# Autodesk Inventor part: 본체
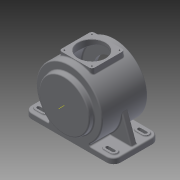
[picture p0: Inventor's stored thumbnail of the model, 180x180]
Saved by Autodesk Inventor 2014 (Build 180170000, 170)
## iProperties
Created: 2015-06
Part Number: 본체
Material: Generic
Document SubType Name: Modeling
Designer: 시험용
Density: 1 g/cm^3
Appearance: Default
Mass: 1210.29 g
Surface Area: 2309.95 cm^2
Volume: 1210.29 cm^3
Author: 시험용
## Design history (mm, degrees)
sketch "스케치1"
  geometry: 1 further point
sketch "스케치2"
  geometry: L1 (-115, 59)-(115, 59); L2 (115, 59)-(115, -59); L3 (115, -59)-(-115, -59); L4 (-115, -59)-(-115, 59); 5 further points
  constraints: 8 end point, 4 midpoint, 2 horizontal alignment, 2 parallel, 2 vertical alignment, 1 horizontal, 1 perpendicular
  dimensions: "d0" = 230 distance of L1.start L1.end; "d1" = 118 distance of L1.end L2.end
extrude "돌출1" new body sketch "스케치2" stored distance "d2" = 14; taper "d3" = 0 deg
sketch "스케치5"
  geometry: L1 (230, -14)-(0, -14) reference; C1 r 85 at (115, 71); 1 further point
  constraints: 1 centre point, 1 tangent, 1 vertical alignment
  dimensions: "d7" = 170 diameter of C1
extrude "돌출3" join sketch "스케치5" distance "d8" = 118; taper "d9" = 0 deg
sketch "스케치6"
  geometry: C1 r 65 at (115, 85); A1 r 85 centre (115, 85) between (161.733, 14) and (68.267, 14) reference; 1 further point
  constraints: 1 centre point, 1 coincident
  dimensions: "d10" = 130 diameter of C1
extrude "돌출4" join sketch "스케치6" distance "d11" = 13; taper "d12" = 0 deg
sketch "스케치7"
  geometry: C1 r 65 at (115, -85); A1 r 85 centre (115, -85) between (68.267, -14) and (161.733, -14) reference; 1 further point
  constraints: 1 centre point, 1 coincident
  dimensions: "d13" = 130 diameter of C1
extrude "돌출5" join sketch "스케치7" distance "d14" = 3; taper "d15" = 0 deg
node "작업 평면1"
sketch "스케치8"
  geometry: L1 (-42.5, 42.5)-(42.5, 42.5); L2 (42.5, 42.5)-(42.5, -42.5); L3 (42.5, -42.5)-(-42.5, -42.5); L4 (-42.5, -42.5)-(-42.5, 42.5); 5 further points
  constraints: 8 end point, 4 midpoint, 2 horizontal alignment, 2 parallel, 2 vertical alignment, 1 horizontal, 1 perpendicular
  dimensions: "d17" = 85 distance of L2.end L3.end; "d18" = 85 distance of L3.end L1.start
extrude "돌출6" join sketch "스케치8" stored distance "d19" = 3; taper "d20" = 0 deg
sketch "스케치9"
  geometry: C1 r 35 at (0, 0); 1 further point
  constraints: 1 centre point, 1 coincident
  dimensions: "d21" = 70 diameter of C1
extrude "돌출7" cut sketch "스케치9" distance "d22" = 20; taper "d23" = 0 deg
sketch "스케치11"
  geometry: L1 (59, 143)-(62, 143) reference; L2 (62, 143)-(62, 13) reference; L3 (35, 166)-(42.5, 166) reference; L4 (42.5, 166)-(42.5, 163) reference; L5 (42.5, 163)-(59, 163) reference; L6 (59, 163)-(59, 143) reference; L7 (-72, 143)-(-59, 143) reference; L8 (-59, 143)-(-59, 163) reference; L9 (-59, 163)-(-42.5, 163) reference; L10 (-42.5, 163)-(-42.5, 166) reference; L11 (-42.5, 166)-(-35, 166) reference; L12 (62, 13)-(59, 13) reference; L13 (59, 13)-(59, -7) reference; L14 (59, -7)-(-59, -7) reference; L15 (-59, -7)-(-59, 13) reference; L16 (-59, 13)-(-72, 13) reference; L17 (-72, 13)-(-72, 143) reference; L18 (-35, 166)-(-35, 146) reference; L19 (-35, 146)-(35, 146) reference; L20 (35, 146)-(35, 166) reference; L21 (-72, 78)-(62, 78); L22 (62, 125.5)-(51, 125.5); L23 (51, 125.5)-(51, 155); L24 (51, 155)-(-51, 155); L25 (-51, 155)-(-51, 110.632); L26 (-51, 110.632)-(-47.5, 109); L27 (-47.5, 109)-(-47.5, 101.5); L28 (-47.5, 101.5)-(-61.5, 101.5); L29 (-61.5, 101.5)-(-61.5, 93); L30 (-61.5, 93)-(-64.5, 93); L31 (-64.5, 93)-(-64.5, 78); 1 further point
  constraints: 22 end point, 7 parallel, 2 midpoint, 2 point on line, 1 perpendicular, 1 vertical
  dimensions: "d51" = 95 diameter of L22 L21; "d52" = 154 diameter of L24 L21; "d53" = 47 diameter of L28 L21; "d54" = 115 deg angle of L26 L25; "d55" = 62 diameter of L26.end L21; "d56" = 3.5 horizontal distance of L26.end L25.end; "d57" = 30 diameter of L30 L21; "d58" = 3 distance from line of L29.end L31; "d59" = 14 horizontal distance of L27.end L29.end; "d60" = 11 distance of L22.start L22.end; "d62" = 102 distance between parallel lines of L23 L25
revolve "회전1" sketch "스케치11" stored, may be unused: angle "d63" = 90 deg
chamfer "모따기1" distance "d64" = 1; stored, may be unused: second distance "d65" = 2, angle "d66" = 45 deg
sketch "스케치12"
  geometry: C1 r 36 at (0, 0) reference; 1 further point
  dimensions: "d67" = 35.5 horizontal distance of C1.centre point (-35.5, 35.5); "d68" = 35.5 horizontal distance of C1.centre point (-35.5, 35.5)
hole "구멍4" sketch "스케치12" at (-35.5, 35.5) diameter "d69" = 3.242; stored, may be unused: countersink angle "d73" = 90 deg, drill point angle "d75" = 118 deg; dims "d70" = 10, "d71" = 47, "d72" = 14, "d74" = 13
sketch "스케치13" dims "d82" = 110
  geometry: C1 r 47.5 at (0, 0) reference; C2 r 65 at (0, 0) reference; 3 further points
  constraints: 2 vertical alignment, 1 coincident, 2 other
hole "구멍5" sketch "스케치13" at (0, -55) diameter "d83" = 3.242; stored, may be unused: countersink angle "d87" = 90 deg, drill point angle "d89" = 0 deg; dims "d84" = 11, "d85" = 47, "d86" = 14, "d88" = 13
sketch "스케치15"
  geometry: L1 (115, -7)-(-115, -7) reference; L2 (-115, -7)-(-115, 7) reference; L3 (-115, 7)-(-46.733, 7) reference; L4 (-42.5, 151.612)-(-42.5, 166) reference; L5 (-42.5, 166)-(-36, 166) reference; L6 (-36, 166)-(-35, 165) reference; L7 (-35, 165)-(-35, 146.586) reference; L8 (35, 146.586)-(35, 165) reference; L9 (35, 165)-(36, 166) reference; L10 (36, 166)-(42.5, 166) reference; L11 (42.5, 166)-(42.5, 151.612) reference; L12 (46.733, 7)-(115, 7) reference; L13 (115, 7)-(115, -7) reference; L14 (-84.87, 73.297)-(-109, 7); A1 r 85 centre (0, 78) between (-42.5, 151.612) and (-46.733, 7) reference; A2 r 85 centre (0, 78) between (46.733, 7) and (42.5, 151.612) reference; A3 r 77 centre (0, 78) between (-35, 146.586) and (35, 146.586) reference; 1 further point
  constraints: 2 end point, 1 point on circle, 1 point on line
  dimensions: "d93" = 110 deg angle of L14 L3; "d94" = 6 distance from line of L14.end L2
feature "리브1" sketch "스케치15" dims "d95" = 1, "d96" = 15, "d97" = 0, "d98" = 0, "d99" = 1, "d100" = 1
sketch "스케치16"
  geometry: L1 (115, -59)-(115, 59) reference; L2 (115, 59)-(46.733, 59) reference; L3 (46.733, -7.5)-(46.733, -59) reference; L4 (115, -59)-(46.733, -59) reference; L5 (115, 59)-(115, -59) reference; L6 (46.733, 59)-(115, 59) reference; L7 (-46.733, 59)-(46.733, 59) reference; L8 (-115, 59)-(-46.733, 59) reference; L9 (-115, -59)-(-115, 59) reference; L10 (-46.733, -59)-(-115, -59) reference; L11 (46.733, -59)-(-46.733, -59) reference; L12 (109, -7.5)-(46.733, -7.5) reference; L13 (109, 7.5)-(109, -7.5) reference; L14 (46.733, 7.5)-(109, 7.5) reference; L15 (46.733, 59)-(46.733, 7.5) reference; L16 (-46.733, 7.5)-(-46.733, 59) reference; L17 (-109, 7.5)-(-46.733, 7.5) reference; L18 (-109, -7.5)-(-109, 7.5) reference; L19 (-46.733, -7.5)-(-109, -7.5) reference; L20 (-46.733, -59)-(-46.733, -7.5) reference; L21 (29.799, -51)-(29.799, 51) reference; L22 (29.799, 51)-(-29.799, 51) reference; L23 (-29.799, 51)-(-29.799, -51) reference; L24 (-29.799, -51)-(29.799, -51) reference; L25 (81, 32)-(97, 32); L26 (97, 50)-(81, 50); L27 (46.733, -7.5)-(46.733, -59) reference; L28 (115, -59)-(46.733, -59) reference; L29 (115, 59)-(115, -59) reference; L30 (46.733, 59)-(115, 59) reference; L31 (-46.733, 59)-(46.733, 59) reference; L32 (-115, 59)-(-46.733, 59) reference; L33 (-115, -59)-(-115, 59) reference; L34 (-46.733, -59)-(-115, -59) reference; L35 (46.733, -59)-(-46.733, -59) reference; L36 (109, -7.5)-(46.733, -7.5) reference; L37 (109, 7.5)-(109, -7.5) reference; L38 (46.733, 7.5)-(109, 7.5) reference; L39 (46.733, 59)-(46.733, 7.5) reference; L40 (-46.733, 7.5)-(-46.733, 59) reference; L41 (-109, 7.5)-(-46.733, 7.5) reference; L42 (-109, -7.5)-(-109, 7.5) reference; L43 (-46.733, -7.5)-(-109, -7.5) reference; L44 (-46.733, -59)-(-46.733, -7.5) reference; L45 (29.799, -51)-(29.799, 51) reference; L46 (29.799, 51)-(-29.799, 51) reference; L47 (-29.799, 51)-(-29.799, -51) reference; L48 (-29.799, -51)-(29.799, -51) reference; A1 r 9 centre (97, 41) between (97, 32) and (97, 50); A2 r 9 centre (81, 41) between (81, 50) and (81, 32); 1 further point
  constraints: 4 end point, 4 point on circle, 4 tangent, 2 centre point, 2 parallel
  dimensions: "d102" = 18 distance from line of L2 A1.centre; "d103" = 16 distance of A2.centre A1.centre; "d104" = 18 distance between parallel lines of L25 L26; "d105" = 18 distance from line of L1 A1.centre
extrude "돌출8" join sketch "스케치16" distance "d106" = 3; taper "d107" = 0 deg
sketch "스케치17"
  geometry: L1 (81, 32)-(97, 32) reference; L2 (97, 50)-(81, 50) reference; L3 (81, 45)-(97, 45); L4 (97, 37)-(81, 37); A1 r 9 centre (97, 41) between (97, 32) and (97, 50) reference; A2 r 9 centre (81, 41) between (81, 50) and (81, 32) reference; A3 r 4 centre (97, 41) between (97, 37) and (97, 45); A4 r 4 centre (81, 41) between (81, 45) and (81, 37); 1 further point
  constraints: 4 end point, 4 point on circle, 2 centre point, 3 other
  dimensions: "d108" = 8 distance between parallel lines of L4 L3
extrude "돌출9" cut sketch "스케치17" stored distance "d109" = 15; taper "d110" = 0 deg
fillet "모깎기1" dims "d111" = 3
fillet "모깎기2" dims "d118" = 18
fillet "모깎기3" dims "d119" = 3
fillet "모깎기4" dims "d120" = 7
fillet "모깎기5" dims "d121" = 3
node "작업 평면5"
  node "작업 평면4"
sketch "스케치19"
  geometry: L1 (-10.5, -44.598)-(-10.5, 20.042) reference; L2 (-56, -44.598)-(-10.5, -44.598) reference; L3 (-56, -82.329)-(-56, -44.598) reference; L4 (-10.5, -82.329)-(-56, -82.329) reference; L5 (-10.5, -39.601)-(-10.5, -82.329) reference; L6 (10.5, -39.601)-(-10.5, -39.601) reference; L7 (10.5, -82.329)-(10.5, -39.601) reference; L8 (56, -82.329)-(10.5, -82.329) reference; L9 (56, -36.727)-(56, -82.329) reference; L10 (10.5, -36.727)-(56, -36.727) reference; L11 (10.5, 20.042)-(10.5, -36.727) reference; L12 (-4.5, 32.161)-(4.5, 32.161) reference; L13 (-45.5, 84.981)-(-45.5, 55.998) reference; L14 (35.5, 84.513)-(-35.5, 84.513) reference; L15 (45.5, 55.998)-(45.5, 84.981) reference; L16 (-35.5, 47.366)-(35.5, 47.366) reference; L17 (51, -77)-(51, 77) reference; L18 (-56, 85)-(-56, -82.329) reference; 7 further points
  constraints: 1 horizontal alignment, 1 midpoint, 1 vertical alignment, 11 other
feature "엠보싱1" sketch "스케치19" dims "d126" = 0.5, "d127" = 0
fillet "모깎기6" dims "d128" = 3
fillet "모깎기7" dims "d129" = 3
fillet "모깎기8" dims "d130" = 3
fillet "모깎기9" dims "d131" = 3
chamfer "모따기2" distance "d132" = 1; stored, may be unused: second distance "d133" = 2, angle "d134" = 45 deg
fillet "모깎기10" dims "d135" = 3
fillet "모깎기11" dims "d136" = 3
chamfer "모따기3" distance "d137" = 1; stored, may be unused: second distance "d138" = 2, angle "d139" = 45 deg
node "솔리드1"
pattern_linear "직사각형 패턴1" dims "d78" = 71, "d81" = 71
pattern_circular "원형 패턴1" dims angle "d91" = 360 deg
mirror "대칭1"
pattern_linear "직사각형 패턴2" dims "d114" = 178, "d117" = 82
node "작업축2"
node "작업 평면3"
node "투영된 루프1"
node "절단 모서리 투영1"
node "절단 모서리 투영2"
node "절단 모서리 투영3"
node "절단 모서리 투영4"
other parameters: "d16" = -173, "d123" = -25 deg, "d124" = -85, "d125" = -0.5
